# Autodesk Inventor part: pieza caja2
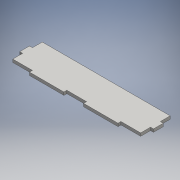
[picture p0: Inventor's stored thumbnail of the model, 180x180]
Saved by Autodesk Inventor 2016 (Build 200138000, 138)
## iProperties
Created: 2016-06
Part Number: pieza caja2
Material: Genérico
Document SubType Name: Modeling
Designer: adm
Density: 1 g/cm^3
Appearance: Valor por defecto
Author: adm
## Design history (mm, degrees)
sketch "Boceto1"
  geometry: L1 (133, 3)-(133, 33); L2 (133, 33)-(3, 33); L3 (58, 3)-(58, 0); L4 (78, 3)-(78, 0); L5 (113, 3)-(113, 0); L6 (23, 3)-(23, 0); L7 (23, 3)-(3, 3); L8 (133, 3)-(113, 3); L9 (78, 3)-(58, 3); L10 (23, 0)-(58, 0); L11 (78, 0)-(113, 0); L12 (0, 13)-(0, 23); L13 (0, 23)-(3, 23); L14 (0, 13)-(3, 13); L15 (3, 3)-(3, 13); L16 (3, 23)-(3, 33); 1 further point
  constraints: 32 end point, 4 parallel, 2 horizontal, 2 perpendicular, 1 vertical
  dimensions: "d5" = 35 distance between parallel lines of L4 L5; "d6" = 35 distance between parallel lines of L3 L6; "d10" = 30 distance between parallel lines of L7 L2; "d13" = 20 distance of L1.start L5.start
extrude "Extrusión1" new body sketch "Boceto1" distance "d14" = 3; taper "d15" = 0 deg
sketch "Boceto2"
  geometry: L1 (-3, 20)-(-3, 10) reference; L2 (0, 10)-(0, 20) reference; L3 (-3, 10)-(0, 10); L4 (0, 10)-(0, 20); L5 (0, 20)-(-3, 20); L6 (-3, 20)-(-3, 10); 1 further point
  constraints: 8 end point, 2 parallel, 1 horizontal, 1 perpendicular
extrude "Extrusión2" join sketch "Boceto2" distance "d16" = 3; taper "d17" = 0 deg
node "Sólido1"
